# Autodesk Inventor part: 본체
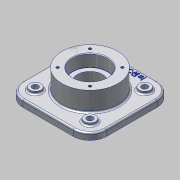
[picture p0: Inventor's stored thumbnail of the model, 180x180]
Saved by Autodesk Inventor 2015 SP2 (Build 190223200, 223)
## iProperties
Created: 2015-07
Part Number: 본체
Material: 알루미늄 6061
Document SubType Name: Modeling
Designer: AMC
Density: 2.7 g/cm^3
Appearance: 알루미늄 - 평지
Mass: 1458.94 g
Surface Area: 797.065 cm^2
Volume: 540.348 cm^3
Author: AMC
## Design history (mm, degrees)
sketch "스케치1"
  geometry: L1 (75, -75)-(-75, -75); L2 (-75, -75)-(-75, 75); L3 (-75, 75)-(75, 75); L4 (75, 75)-(75, -75); L5 (75, -75)-(-75, 75); L6 (-75, -75)-(75, 75); 1 further point
  constraints: 12 end point, 2 midpoint, 2 parallel, 1 horizontal, 1 perpendicular
  dimensions: "d0" = 150 distance of L2.end L3.end; "d1" = 150 distance of L1.end L2.end
extrude "돌출1" new body sketch "스케치1" distance "d2" = 12; taper "d3" = 0 deg
sketch "스케치2"
  geometry: C1 r 50 at (0, 0); 1 further point
  constraints: 1 centre point, 1 coincident
  dimensions: "d4" = 100 diameter of C1
extrude "돌출2" join sketch "스케치2" distance "d5" = 35; taper "d6" = 0 deg
sketch "스케치3"
  geometry: C1 r 50 at (0, 0); 1 further point
  constraints: 1 centre point, 1 coincident
  dimensions: "d7" = 100 diameter of C1
extrude "돌출3" join sketch "스케치3" distance "d8" = 23; taper "d9" = 0 deg
hole "구멍1" diameter "d12" = 45; stored, may be unused: countersink angle "d16" = 90 deg, drill point angle "d18" = 0 deg; dims "d10" = 10, "d11" = 10, "d13" = 6, "d14" = 62, "d15" = 22, "d17" = 8
hole "구멍2" diameter "d21" = 45; stored, may be unused: countersink angle "d25" = 90 deg, drill point angle "d27" = 0 deg; dims "d19" = 10, "d20" = 10, "d22" = 6, "d23" = 62, "d24" = 22, "d26" = 8
fillet "모깎기3" dims "d33" = 30
sketch "스케치8"
  geometry: C1 r 10 at (-49, 49); C2 r 10 at (-49, -49); C3 r 10 at (49, -49); C4 r 10 at (49, 49); 1 further point
  constraints: 4 centre point, 1 horizontal alignment, 9 other
  dimensions: "d34" = 20 diameter of C1; "d37" = 360 deg dimension on point (0, 0) C1.centre (derived); "d39" = 98 distance of C4.centre C1.centre; "d40" = 98 distance of C2.centre C1.centre (derived)
extrude "돌출4" join sketch "스케치8" distance "d41" = 5; taper "d42" = 0 deg
hole "구멍3" diameter "d45" = 11; stored, may be unused: countersink angle "d49" = 90 deg, drill point angle "d51" = 0 deg; dims "d43" = 10, "d44" = 10, "d46" = 6, "d47" = 62, "d48" = 22, "d50" = 8
hole "구멍4" diameter "d54" = 11; stored, may be unused: countersink angle "d58" = 90 deg, drill point angle "d60" = 0 deg; dims "d52" = 10, "d53" = 10, "d55" = 6, "d56" = 62, "d57" = 22, "d59" = 8
hole "구멍5" diameter "d63" = 11; stored, may be unused: countersink angle "d67" = 90 deg, drill point angle "d69" = 0 deg; dims "d61" = 10, "d62" = 10, "d64" = 6, "d65" = 62, "d66" = 22, "d68" = 8
hole "구멍6" diameter "d72" = 11; stored, may be unused: countersink angle "d76" = 90 deg, drill point angle "d78" = 0 deg; dims "d70" = 10, "d71" = 10, "d73" = 6, "d74" = 62, "d75" = 22, "d77" = 8
fillet "모깎기4" dims "d79" = 3
fillet "모깎기5" dims "d80" = 3
fillet "모깎기6" dims "d81" = 0.3
chamfer "모따기1" distance "d82" = 1; stored, may be unused: second distance "d83" = 2, angle "d84" = 45 deg
chamfer "모따기2" distance "d85" = 1; stored, may be unused: second distance "d86" = 2, angle "d87" = 45 deg
sketch "스케치9"
  geometry: L1 (0, 0)-(41, 0); L2 (0, 0)-(28.991, 28.991); A1 r 41 centre (0, 0) between (41, 0) and (28.991, 28.991); 2 further points
  constraints: 4 end point, 2 coincident, 2 point on circle, 1 centre point, 1 horizontal
  dimensions: "d88" = 82 diameter of A1; "d89" = 45 deg angle of L1 L2
hole "구멍7" sketch "스케치9" at (28.991, 28.991) diameter "d90" = 4.917; stored, may be unused: countersink angle "d94" = 90 deg, drill point angle "d96" = 118 deg; dims "d91" = 10, "d92" = 62, "d93" = 22, "d95" = 13
sketch "스케치10"
  geometry: L1 (0, 0)-(41, 0); L2 (0, 0)-(28.991, 28.991); A1 r 41 centre (0, 0) between (41, 0) and (28.991, 28.991); 2 further points
  constraints: 4 end point, 2 coincident, 2 point on circle, 1 centre point, 1 horizontal
  dimensions: "d100" = 82 diameter of A1; "d101" = 45 deg angle of L1 L2
hole "구멍8" sketch "스케치10" at (28.991, 28.991) diameter "d102" = 4.917; stored, may be unused: countersink angle "d106" = 90 deg, drill point angle "d108" = 118 deg; dims "d103" = 10, "d104" = 62, "d105" = 22, "d107" = 13
sketch "스케치11"
  geometry: 2 further points
  constraints: 1 vertical alignment, 1 other
  dimensions: "d115" = 65 distance of point (0, 0) point (0, 65)
feature "엠보싱1" sketch "스케치11" dims "d0" = 150, "d1" = 150, "d20" = 10, "d116" = 1, "d117" = 0
node "솔리드1"
pattern_circular "원형 패턴2" dims angle "d110" = 360 deg
pattern_circular "원형 패턴3" dims angle "d113" = 360 deg
